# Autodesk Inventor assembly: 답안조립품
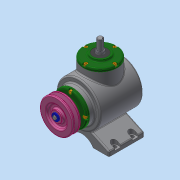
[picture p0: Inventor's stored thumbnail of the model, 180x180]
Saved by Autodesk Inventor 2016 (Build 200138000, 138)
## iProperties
Created: 2021-04
Part Number: 답안조립품
Document SubType Name: Assembly
Designer: User
Author: User
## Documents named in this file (17)
- C:\Users\User\Desktop\710407V1009\답안조립품.iam
- C:\Users\User\Desktop\710407V1009\본체.ipt
- C:\Users\User\Desktop\710407V1009\메인 베벨기어.ipt
- C:\Users\User\Desktop\710407V1009\메인 축.ipt
- 메인 축.ipt
- C:\Users\User\Desktop\710407V1009\키 5 x 5 x 14.ipt
- C:\Users\User\Desktop\710407V1009\베어링 6203.ipt
- C:\Users\User\Desktop\710407V1009\커버.ipt
- C:\Users\User\Desktop\710407V1009\서브 베벨기어.ipt
- C:\Users\User\Desktop\710407V1009\서브 축.ipt
- 서브 축.ipt
- C:\Users\User\Desktop\710407V1009\키 4 x 4 x 14.ipt
- C:\Users\User\Desktop\710407V1009\오일실 17 x 32 x 8.ipt
- C:\Users\User\Desktop\710407V1009\볼트 M4 x 10.ipt
- C:\Users\User\Desktop\710407V1009\V-벨트풀리.ipt
- C:\Users\User\Desktop\710407V1009\와셔 4 x 16.ipt
- C:\Users\User\Desktop\710407V1009\육각볼트 M4 x 8.ipt
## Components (1 placed, 1 different names)
1. V-벨트풀리:1
